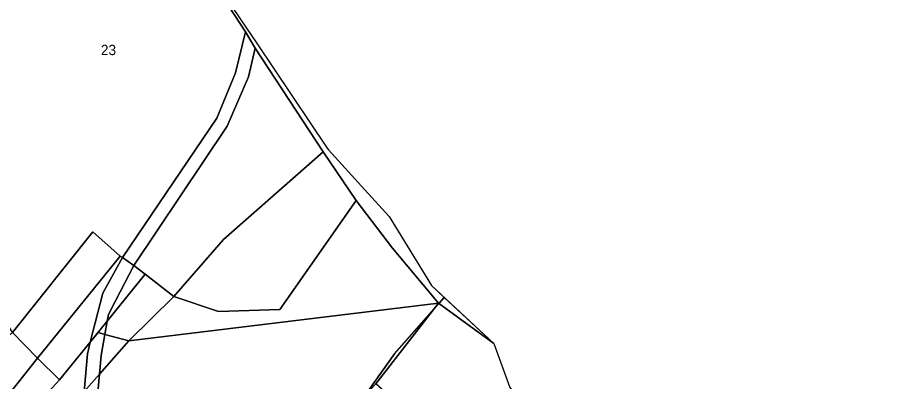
# Model space of a CAD drawing. Extents: x -521261 to -517465, y -1182764 to -1179456.
# Drawn here: x -518673.2 to -518252.9, y -1181298.5 to -1181121.3 of the extents above; entities that cross this region are included whole.
import ezdxf

# ---------------------------------------------------------------- set-up
doc = ezdxf.new("R2010")
doc.units = 0
for name, color, linetype in [('95560013', 7, 'Continuous'), ('95610013', 7, 'Continuous'), ('95620013', 7, 'Continuous'), ('95640013', 7, 'Continuous'), ('95660013', 7, 'Continuous')]:
    doc.layers.add(name, color=color, linetype=linetype)

msp = doc.modelspace()

# ---------------------------------------------------------------- linework, layer by layer
at = {"layer": '95560013'}
for points in [[(-518675.54, -1181274.63), (-518663.33, -1181287.08), (-518693.19, -1181324.53), (-518718.13, -1181347.7), (-518735.27, -1181357.29), (-518763.95, -1181367.17), (-518836.89, -1181372.83), (-518890.74, -1181379.2), (-519047.36, -1181389.95), (-519034.31, -1181361.29), (-518927.65, -1181352.54), (-518859.29, -1181344.94), (-518796.86, -1181341.76), (-518778.15, -1181339.19), (-518762.37, -1181334.9), (-518738.07, -1181325.54), (-518712.97, -1181307.58)], [(-518637.63, -1181279.33), (-518639.08, -1181284.96), (-518640.69, -1181303.28), (-518681.4, -1181349.69), (-518702.55, -1181373.11), (-518720.57, -1181388.36), (-518749.09, -1181398.29), (-518802.62, -1181403.53), (-518803.83, -1181388.28), (-518755.97, -1181382.48), (-518726.45, -1181370.33), (-518708.77, -1181358.68), (-518652.62, -1181297.59)], [(-518652.62, -1181297.59), (-518708.77, -1181358.68), (-518726.45, -1181370.33), (-518755.97, -1181382.48), (-518803.83, -1181388.28), (-518841.69, -1181390.76), (-518892.4, -1181397.12), (-519048.38, -1181403.77), (-519047.36, -1181389.95), (-518890.74, -1181379.2), (-518836.89, -1181372.83), (-518763.95, -1181367.17), (-518735.27, -1181357.29), (-518718.13, -1181347.7), (-518693.19, -1181324.53), (-518663.33, -1181287.08)]]:
    msp.add_lwpolyline(points, close=True, dxfattribs=at)
at = {"layer": '95610013'}
for points in [[(-518618.91, -1181278.73), (-518468.13, -1181260.3), (-518498.65, -1181299.5), (-518516.46, -1181318.54), (-518537.66, -1181343.4), (-518554.51, -1181362.62), (-518557.46, -1181365.95), (-518560.15, -1181368.8), (-518594.4, -1181408.92), (-518599.62, -1181415.62), (-518607.63, -1181409.87), (-518631.22, -1181391.42), (-518641.12, -1181383.21), (-518633.23, -1181294.88)], [(-518630.55, -1181275.53), (-518618.91, -1181278.73), (-518633.23, -1181294.88), (-518632.43, -1181285.85)]]:
    msp.add_lwpolyline(points, close=True, dxfattribs=at)
at = {"layer": '95620013'}
msp.add_lwpolyline([(-518572.75, -1181111.95), (-518562.06, -1181128.41), (-518566.98, -1181148.39), (-518576.06, -1181170.33), (-518621.98, -1181238.21), (-518623.17, -1181237.54), (-518636.38, -1181225.73), (-518675.54, -1181274.63), (-518689.45, -1181251.43), (-518697.49, -1181238.21), (-518703.33, -1181228.32), (-518710.23, -1181210.23), (-518718.38, -1181201.7), (-518760.41, -1181218.29), (-518786.29, -1181205.72), (-518785.86, -1181197.97), (-518785.42, -1181185.66), (-518796.94, -1181166.4), (-518799.71, -1181127.22), (-518796.51, -1181107.45)], dxfattribs=at)
for points in [[(-518560.63, -1181150.29), (-518557.39, -1181136.36), (-518524.34, -1181186.8), (-518572.79, -1181229.45), (-518597, -1181257.08), (-518610.97, -1181246.25), (-518616.48, -1181241.98), (-518570.97, -1181174.25)], [(-518524.34, -1181186.8), (-518508.25, -1181210.43), (-518545.39, -1181263.42), (-518575.24, -1181264.38), (-518597, -1181257.08), (-518572.79, -1181229.45)], [(-518508.25, -1181210.43), (-518490.58, -1181233.66), (-518468.13, -1181260.3), (-518618.91, -1181278.73), (-518597, -1181257.08), (-518575.24, -1181264.38), (-518545.39, -1181263.42)], [(-518623.17, -1181237.54), (-518663.33, -1181287.08), (-518675.54, -1181274.63), (-518636.38, -1181225.73)], [(-518621.98, -1181238.21), (-518631.51, -1181255.55), (-518637.63, -1181279.33), (-518652.62, -1181297.59), (-518663.33, -1181287.08), (-518623.17, -1181237.54)]]:
    msp.add_lwpolyline(points, close=True, dxfattribs=at)
at = {"layer": '95640013'}
for points in [[(-518612.92, -1181016.94), (-518611.72, -1181039.62), (-518601.93, -1181076.25), (-518571.79, -1181111.44), (-518561.65, -1181126.57), (-518556.81, -1181133.74), (-518522.41, -1181184.93), (-518521.66, -1181185.76), (-518503.98, -1181205.23), (-518492.13, -1181218.29), (-518471.48, -1181251.81), (-518441.26, -1181279.93), (-518468.13, -1181260.3), (-518490.58, -1181233.66), (-518508.25, -1181210.43), (-518524.34, -1181186.8), (-518557.39, -1181136.36), (-518562.06, -1181128.41), (-518572.75, -1181111.95), (-518603.1, -1181077.1), (-518613.17, -1181039.84), (-518614.4, -1181017.6)], [(-518562.06, -1181128.41), (-518557.39, -1181136.36), (-518560.63, -1181150.29), (-518570.97, -1181174.25), (-518616.48, -1181241.98), (-518621.98, -1181238.21), (-518576.06, -1181170.33), (-518566.98, -1181148.39)], [(-518621.98, -1181238.21), (-518616.48, -1181241.98), (-518625.43, -1181259.15), (-518628.78, -1181265.87), (-518629.36, -1181269.07), (-518637.63, -1181279.33), (-518631.51, -1181255.55)], [(-518616.48, -1181241.98), (-518610.97, -1181246.25), (-518629.36, -1181269.07), (-518628.78, -1181265.87), (-518625.43, -1181259.15)], [(-518610.97, -1181246.25), (-518597, -1181257.08), (-518618.91, -1181278.73), (-518630.55, -1181275.53), (-518629.36, -1181269.07)], [(-518468.13, -1181260.3), (-518441.26, -1181279.93), (-518433.35, -1181301.32), (-518402.58, -1181338.76), (-518398.47, -1181343.3), (-518421.07, -1181367.82), (-518498.65, -1181299.5)], [(-518630.55, -1181275.53), (-518632.43, -1181285.85), (-518633.23, -1181294.88), (-518640.69, -1181303.28), (-518639.08, -1181284.96), (-518637.63, -1181279.33), (-518629.36, -1181269.07)], [(-518640.69, -1181303.28), (-518633.23, -1181294.88), (-518641.12, -1181383.21), (-518647.24, -1181378.13)]]:
    msp.add_lwpolyline(points, close=True, dxfattribs=at)
at = {"layer": '95660013'}
for points in [[(-518571.79, -1181111.44), (-518561.65, -1181126.57), (-518556.81, -1181133.74), (-518522.41, -1181184.93), (-518521.66, -1181185.76), (-518503.98, -1181205.23), (-518492.13, -1181218.29), (-518471.48, -1181251.81), (-518465.3, -1181257.55), (-518467.67, -1181260.24), (-518468.13, -1181260.3), (-518618.91, -1181278.73), (-518630.55, -1181275.53), (-518633.84, -1181274.63), (-518637.63, -1181279.33), (-518652.62, -1181297.59), (-518663.33, -1181287.08), (-518675.54, -1181274.63)], [(-518675.54, -1181274.63), (-518663.33, -1181287.08), (-518652.62, -1181297.59), (-518637.63, -1181279.33), (-518633.84, -1181274.63), (-518630.55, -1181275.53), (-518618.91, -1181278.73), (-518468.13, -1181260.3), (-518467.67, -1181260.24), (-518489.5, -1181285), (-518527.5, -1181338.5), (-518571, -1181405.5), (-518593.5, -1181450.5), (-518600, -1181473), (-518602, -1181509), (-518591, -1181563), (-518568, -1181628)], [(-518568, -1181628), (-518591, -1181563), (-518602, -1181509), (-518600, -1181473), (-518593.5, -1181450.5), (-518571, -1181405.5), (-518527.5, -1181338.5), (-518489.5, -1181285), (-518465.3, -1181257.55), (-518441.26, -1181279.93), (-518433.35, -1181301.32), (-518402.58, -1181338.76), (-518398.47, -1181343.3), (-518358.32, -1181387.58), (-518310.97, -1181412.15), (-518263.14, -1181433.58), (-518259.28, -1181435.3), (-518258.36, -1181435.71), (-518252.86, -1181438.18), (-518256, -1181442), (-518292, -1181501.5), (-518357, -1181605.5)]]:
    msp.add_lwpolyline(points, dxfattribs=at)

# ---------------------------------------------------------------- texts
msp.add_text('23', height=5, rotation=0, dxfattribs=at).set_placement((-518632.51, -1181139.73))

doc.saveas('drawing.dxf')
